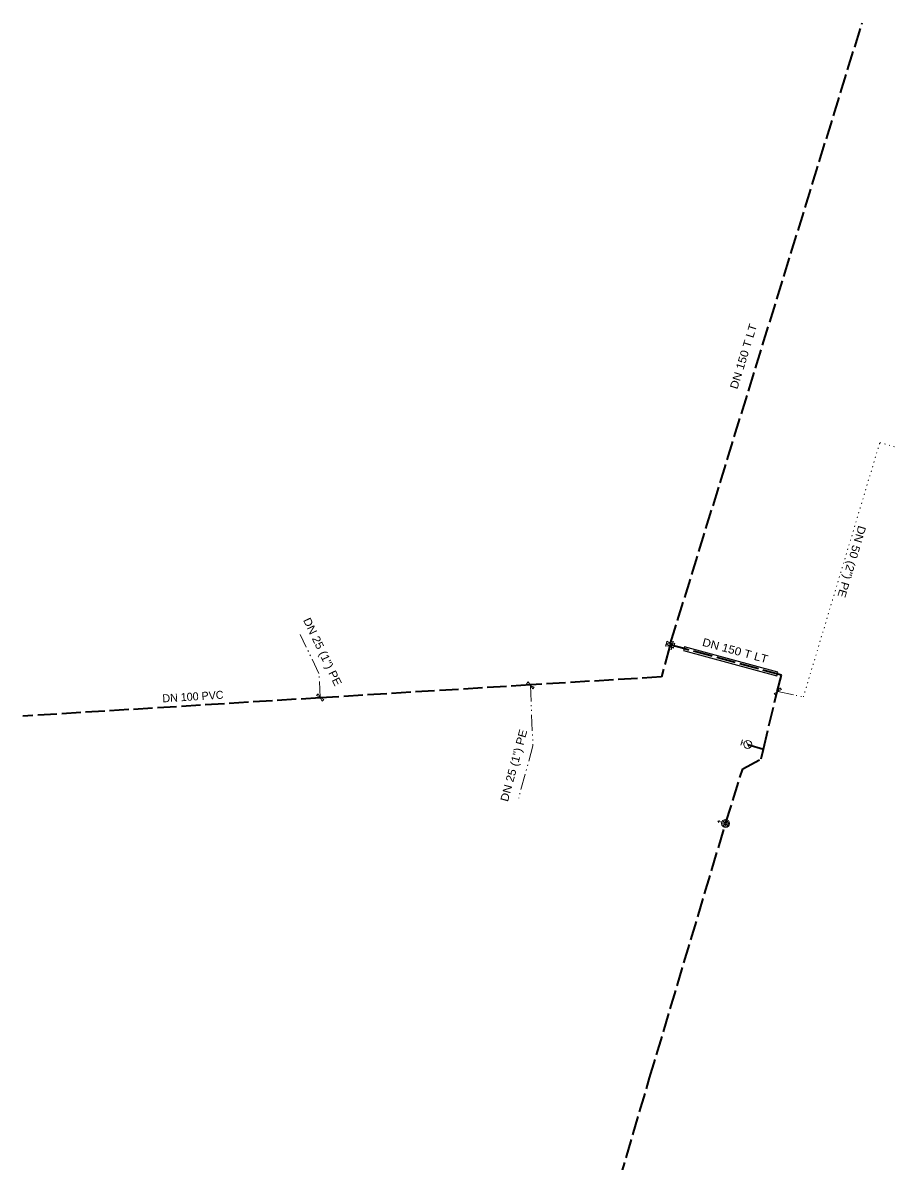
# Model space of a CAD drawing. Extents: x -645287 to -645115, y -1043737 to -1043439.
# Drawn here: x -645265.6 to -645156.5, y -1043581.1 to -1043438.8 of the extents above; entities that cross this region are included whole.
import ezdxf
from ezdxf.enums import TextEntityAlignment as Align

# ---------------------------------------------------------------- set-up
doc = ezdxf.new("R2010")
doc.units = 0
doc.header["$LTSCALE"] = 0.4
for name, pattern in [('DASH_DOUBLE_DOT', [9.2, 5, -1.2, 0.3, -1.2, 0.3, -1.2]), ('DOTTED', [1.5, 0.3, -1.2]), ('LONG_DASHED', [7.5, 6, -1.5])]:
    doc.linetypes.add(name, pattern=pattern)
for name, color, linetype, lineweight in [('10', 7, 'Continuous', 13), ('21', 7, 'LONG_DASHED', 35), ('32', 7, 'DASH_DOUBLE_DOT', 13), ('51', 7, 'Continuous', 25)]:
    doc.layers.add(name, color=color, linetype=linetype, lineweight=lineweight)
doc.layers.add('29', color=7, linetype='Continuous')
doc.layers.add('39', color=7, linetype='Continuous')

msp = doc.modelspace()

# ---------------------------------------------------------------- linework, layer by layer
at = {"layer": '10'}
for p, q in [((-645175.797, -1043529.131), (-645175.593, -1043528.462)), ((-645174.695, -1043529.472), (-645175.164, -1043528.589)), ((-645175.408, -1043528.884), (-645175.695, -1043528.796)), ((-645178.658, -1043538.624), (-645178.482, -1043538.529))]:
    msp.add_line(p, q, dxfattribs=at)
for points in [[(-645184.159, -1043516.691), (-645185.201, -1043516.75), (-645185.131, -1043516.458), (-645184.228, -1043516.983)], [(-645184.068, -1043516.37), (-645185.112, -1043516.409), (-645185.036, -1043516.119), (-645184.144, -1043516.661)], [(-645184.477, -1043517.151), (-645184.503, -1043516.108), (-645184.213, -1043516.187), (-645184.767, -1043517.072)], [(-645201.632, -1043521.859), (-645202.588, -1043521.438), (-645202.393, -1043521.21), (-645201.827, -1043522.087)], [(-645227.941, -1043523.402), (-645228.861, -1043522.909), (-645228.65, -1043522.697), (-645228.153, -1043523.615)], [(-645170.937, -1043521.955), (-645171.428, -1043522.876), (-645171.641, -1043522.665), (-645170.724, -1043522.167)]]:
    msp.add_lwpolyline(points, close=True, dxfattribs=at)
msp.add_lwpolyline([(-645178.179, -1043538.767), (-645178.658, -1043538.624), (-645178.563, -1043538.8)], dxfattribs=at)
for centre, radius in [((-645174.9301, -1043529.03), 0.5), ((-645177.6997, -1043538.9105), 0.5), ((-645177.6997, -1043538.9105), 0.35), ((-645177.6997, -1043538.9105), 0.2)]:
    msp.add_circle(centre, radius, dxfattribs=at)
at = {"layer": '21'}
for p, q in [((-645184.59, -1043516.39), (-645160.621, -1043438.84)), ((-645184.61, -1043516.57), (-645184.68, -1043516.72)), ((-645202.112, -1043521.598), (-645228.398, -1043523.206)), ((-645172.975, -1043529.628), (-645171.239, -1043522.404)), ((-645174.93, -1043529.03), (-645172.975, -1043529.628))]:
    msp.add_line(p, q, dxfattribs=at)
for points in [[(-645184.68, -1043516.72), (-645185.73, -1043520.59), (-645202.112, -1043521.598)], [(-645184.49, -1043516.63), (-645184.61, -1043516.57), (-645184.59, -1043516.39)], [(-645171.239, -1043522.404), (-645170.709, -1043520.382), (-645182.92, -1043517.06), (-645184.49, -1043516.63)], [(-645228.398, -1043523.206), (-645265.605, -1043525.505), (-645265.605, -1043525.505)], [(-645177.7, -1043538.91), (-645175.56, -1043532.07), (-645173.26, -1043530.84), (-645172.975, -1043529.628)], [(-645198.636, -1043609.473), (-645187.2, -1043570.69), (-645177.7, -1043538.91)]]:
    msp.add_lwpolyline(points, dxfattribs=at)
at = {"layer": '32'}
for p, q in [((-645228.554, -1043520.177), (-645230.899, -1043515.294)), ((-645202.112, -1043521.598), (-645202.11, -1043521.648)), ((-645202.11, -1043521.648), (-645201.795, -1043529.196)), ((-645171.239, -1043522.404), (-645171.182, -1043522.416)), ((-645171.182, -1043522.416), (-645168.895, -1043522.901)), ((-645228.398, -1043523.206), (-645228.401, -1043523.156)), ((-645201.795, -1043529.196), (-645203.579, -1043535.735))]:
    msp.add_line(p, q, dxfattribs=at)
at = {"layer": '32', "linetype": 'DOTTED'}
msp.add_lwpolyline([(-645168.895, -1043522.901), (-645167.978, -1043523.099), (-645158.412, -1043491.319), (-645156.483, -1043491.871)], dxfattribs=at)
at = {"layer": '32'}
msp.add_lwpolyline([(-645228.401, -1043523.156), (-645228.554, -1043520.177), (-645228.554, -1043520.177)], dxfattribs=at)
at = {"layer": '51'}
msp.add_lwpolyline([(-645182.986, -1043517.301), (-645171.28, -1043520.466), (-645171.179, -1043520.012), (-645182.854, -1043516.819)], close=True, dxfattribs=at)

# ---------------------------------------------------------------- texts
at = {"layer": '29', "width": 1.1}
for rotation, p in [(72.825, (-645174.9908, -1043480.6846)), (344.781, (-645176.6353, -1043517.784))]:
    msp.add_text('DN 150 T LT', height=1, rotation=rotation, dxfattribs=at).set_placement(p, align=Align.CENTER)
at = {"layer": '29'}
msp.add_text('DN 100 PVC', height=1, rotation=3.542, dxfattribs=at).set_placement((-645244.2899, -1043523.5423), align=Align.CENTER)
at = {"layer": '39', "width": 1.1}
for s, rotation, p in [('DN 50 (2") PE', 253.467, (-645162.3973, -1043506.0497)), ('DN 25 (1") PE', 295.652, (-645228.5636, -1043517.6715)), ('DN 25 (1") PE', 74.743, (-645203.714, -1043531.7896))]:
    msp.add_text(s, height=1, rotation=rotation, dxfattribs=at).set_placement(p, align=Align.CENTER)

doc.saveas('drawing.dxf')
